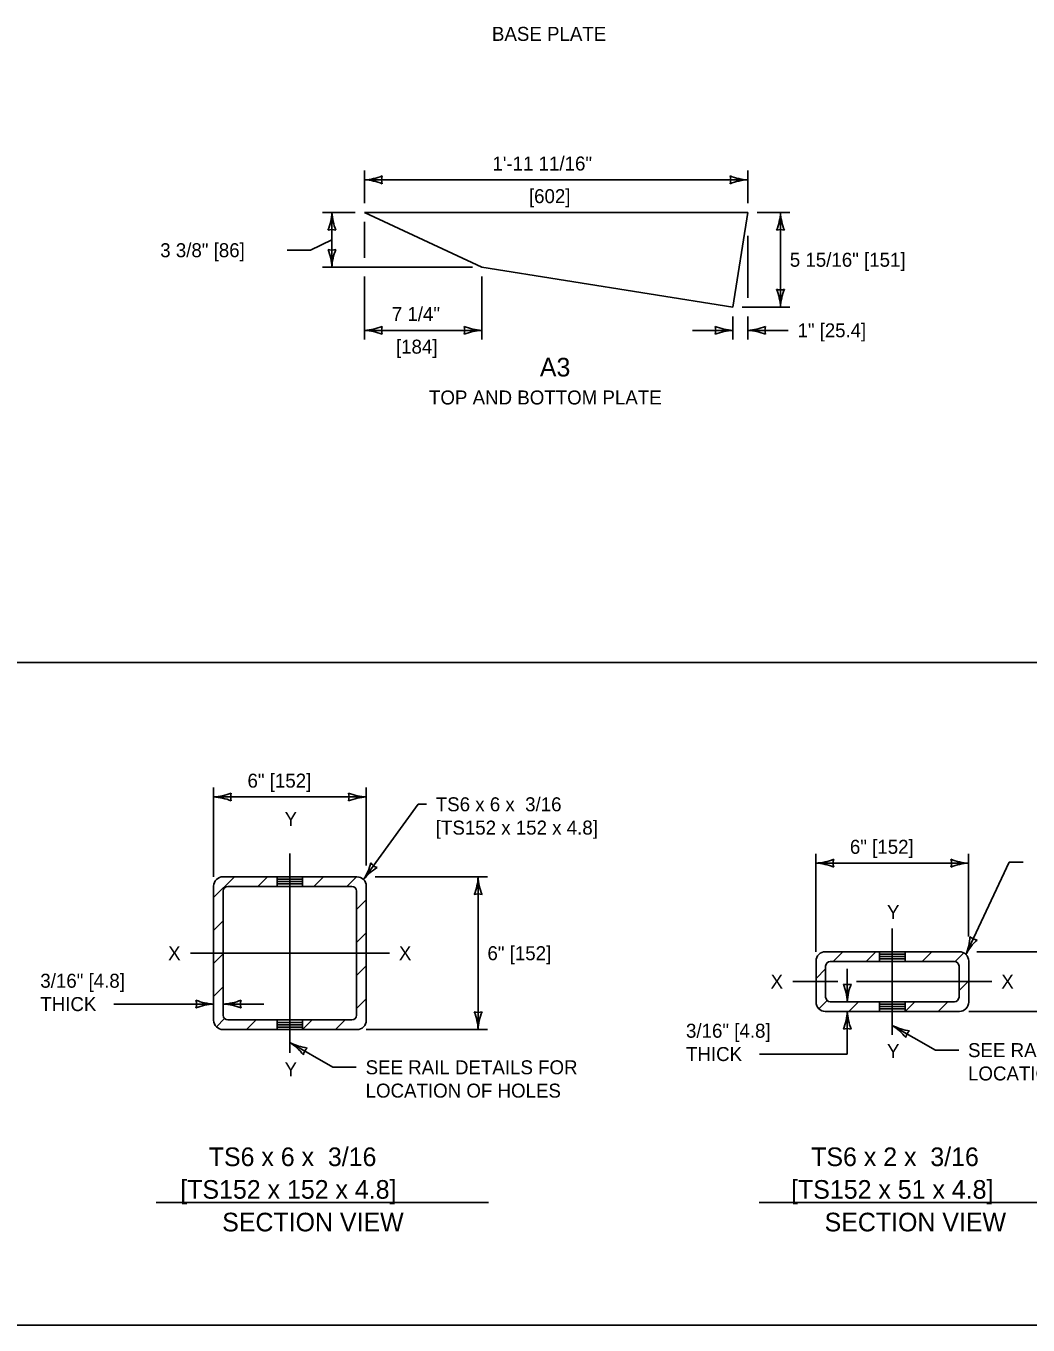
# Model space of a CAD drawing. Extents: x 49991.4 to 50021, y 49987.6 to 50011.4.
# Drawn here: x 50005.99 to 50010.29, y 49987.8 to 49993.37 of the extents above; entities that cross this region are included whole.
import ezdxf

# ---------------------------------------------------------------- set-up
doc = ezdxf.new("R2010")
doc.units = 0
for name, color, linetype in [('Level 1', 7, 'Continuous'), ('Level 2', 7, 'Continuous'), ('Level 3', 7, 'Continuous'), ('Level 4', 7, 'Continuous'), ('Level 5', 7, 'Continuous')]:
    doc.layers.add(name, color=color, linetype=linetype)

msp = doc.modelspace()

# ---------------------------------------------------------------- linework, layer by layer
at = {"layer": 'Level 1'}
for p, q in [((50009.0844, 49992.5698), (50007.4395, 49992.5698)), ((50007.9429, 49992.335), (50007.4395, 49992.5698)), ((50009.0844, 49992.5698), (50009.0202, 49992.1644)), ((50009.0202, 49992.1644), (50007.9429, 49992.335)), ((50005.9232, 49990.6395), (50016.7501, 49990.6395)), ((50006.7919, 49989.6315), (50006.8814, 49989.721)), ((50006.8319, 49989.721), (50007.407, 49989.7209)), ((50006.9814, 49989.6796), (50007.0228, 49989.721)), ((50007.0644, 49989.7102), (50007.1739, 49989.7102)), ((50007.0644, 49989.7002), (50007.1739, 49989.7002)), ((50007.0644, 49989.6902), (50007.1739, 49989.6902)), ((50007.222, 49989.6795), (50007.2634, 49989.7209)), ((50007.3634, 49989.6795), (50007.4048, 49989.7209)), ((50006.7919, 49989.681), (50006.7919, 49989.1058)), ((50006.8333, 49989.1271), (50006.8333, 49989.6596)), ((50006.8533, 49989.6796), (50007.3856, 49989.6795)), ((50007.4056, 49989.6595), (50007.4056, 49989.1272)), ((50007.447, 49989.6809), (50007.447, 49989.1057)), ((50007.4056, 49989.5802), (50007.447, 49989.6216)), ((50006.7919, 49989.49), (50006.8333, 49989.5314)), ((50007.4056, 49989.4388), (50007.447, 49989.4802)), ((50006.7919, 49989.3486), (50006.8333, 49989.39)), ((50009.3768, 49989.3598), (50009.3768, 49989.1836)), ((50009.4168, 49989.3998), (50009.9919, 49989.3998)), ((50009.4382, 49989.3584), (50009.9705, 49989.3584)), ((50009.4501, 49989.3584), (50009.4916, 49989.3998)), ((50009.5916, 49989.3584), (50009.633, 49989.3998)), ((50009.6495, 49989.3891), (50009.7589, 49989.3891)), ((50009.6495, 49989.3791), (50009.7589, 49989.3791)), ((50009.6495, 49989.3691), (50009.7589, 49989.3691)), ((50009.8323, 49989.3584), (50009.8737, 49989.3998)), ((50009.9735, 49989.3581), (50010.0105, 49989.3952)), ((50010.0319, 49989.3598), (50010.0319, 49989.1836)), ((50007.4056, 49989.2974), (50007.447, 49989.3388)), ((50009.3768, 49989.285), (50009.4182, 49989.3264)), ((50009.4182, 49989.205), (50009.4182, 49989.3384)), ((50009.9905, 49989.3384), (50009.9905, 49989.205)), ((50006.7919, 49989.2072), (50006.8333, 49989.2486)), ((50009.9905, 49989.2337), (50010.0319, 49989.2751)), ((50007.4056, 49989.156), (50007.447, 49989.1974)), ((50009.3885, 49989.1553), (50009.424, 49989.1909)), ((50009.4168, 49989.1436), (50009.9919, 49989.1436)), ((50009.9705, 49989.185), (50009.4382, 49989.185)), ((50009.5182, 49989.1436), (50009.5596, 49989.185)), ((50009.6495, 49989.1743), (50009.7589, 49989.1743)), ((50009.6495, 49989.1643), (50009.7589, 49989.1643)), ((50009.6495, 49989.1543), (50009.7589, 49989.1543)), ((50009.7589, 49989.1436), (50009.8004, 49989.185)), ((50009.9004, 49989.1436), (50009.9418, 49989.185)), ((50006.8036, 49989.0775), (50006.8391, 49989.113)), ((50007.3856, 49989.1072), (50006.8533, 49989.1071)), ((50006.9333, 49989.0658), (50006.9746, 49989.1071)), ((50007.0644, 49989.0964), (50007.1739, 49989.0964)), ((50007.0644, 49989.0864), (50007.1739, 49989.0864)), ((50007.1739, 49989.0658), (50007.2153, 49989.1072)), ((50007.3153, 49989.0657), (50007.3568, 49989.1072)), ((50007.407, 49989.0657), (50006.8319, 49989.0658)), ((50007.0644, 49989.0764), (50007.1739, 49989.0764))]:
    msp.add_line(p, q, dxfattribs=at)
msp.add_lwpolyline([(49999.3835, 49998.9992), (50016.7501, 49998.9992), (50016.7501, 49987.7988), (49999.3835, 49987.7988)], close=True, dxfattribs=at)
for centre, radius, start, end in [((50006.8319, 49989.681), 0.04, 90, 180), ((50007.407, 49989.6809), 0.04, 0, 90), ((50006.8533, 49989.6596), 0.02, 90, 180), ((50007.3856, 49989.6595), 0.02, 0, 90), ((50009.4168, 49989.3598), 0.04, 90, 180), ((50009.4382, 49989.3384), 0.02, 90, 180), ((50009.9705, 49989.3384), 0.02, 0, 90), ((50009.9919, 49989.3598), 0.04, 0, 90), ((50009.4382, 49989.205), 0.02, 180, 270), ((50009.9705, 49989.205), 0.02, 270, 0), ((50009.4168, 49989.1836), 0.04, 180, 270), ((50009.9919, 49989.1836), 0.04, 270, 0), ((50006.8319, 49989.1058), 0.04, 180, 270), ((50006.8533, 49989.1271), 0.02, 180, 270), ((50007.3856, 49989.1272), 0.02, 270, 0), ((50007.407, 49989.1057), 0.04, 270, 0)]:
    msp.add_arc(centre, radius, start, end, dxfattribs=at)
at = {"layer": 'Level 2'}
for p, q in [((50006.5456, 49988.3243), (50007.9708, 49988.3243)), ((50009.1328, 49988.3243), (50010.558, 49988.3243))]:
    msp.add_line(p, q, dxfattribs=at)
at = {"layer": 'Level 3'}
for p, q in [((50007.4395, 49992.6098), (50007.4395, 49992.7498)), ((50007.4395, 49992.7098), (50009.0844, 49992.7098)), ((50009.0844, 49992.6098), (50009.0844, 49992.7498)), ((50007.3995, 49992.5698), (50007.2595, 49992.5698)), ((50007.2995, 49992.5698), (50007.2995, 49992.335)), ((50009.1244, 49992.5698), (50009.2644, 49992.5698)), ((50009.2244, 49992.5698), (50009.2244, 49992.1644)), ((50007.4395, 49992.5298), (50007.4395, 49992.375)), ((50007.2995, 49992.4524), (50007.2071, 49992.408)), ((50009.0844, 49992.4698), (50009.0844, 49992.2044)), ((50007.2071, 49992.408), (50007.1071, 49992.408)), ((50007.9029, 49992.335), (50007.2595, 49992.335)), ((50007.4395, 49992.295), (50007.4395, 49992.0244)), ((50007.9429, 49992.295), (50007.9429, 49992.0244)), ((50009.0602, 49992.1644), (50009.2644, 49992.1644)), ((50009.0202, 49992.1244), (50009.0202, 49992.0244)), ((50009.0844, 49992.1244), (50009.0844, 49992.0244)), ((50007.4395, 49992.0644), (50007.9429, 49992.0644)), ((50009.0202, 49992.0644), (50008.8468, 49992.0644)), ((50009.0844, 49992.0644), (50009.2579, 49992.0644)), ((50006.7917, 49989.721), (50006.7917, 49990.1033)), ((50007.4468, 49989.7689), (50007.4468, 49990.1033)), ((50006.7917, 49990.0633), (50007.4468, 49990.0633)), ((50007.4352, 49989.7092), (50007.6694, 49990.0319)), ((50007.7051, 49990.0319), (50007.6694, 49990.0319)), ((50009.3767, 49989.3998), (50009.3767, 49989.8195)), ((50010.0318, 49989.4647), (50010.0318, 49989.8195)), ((50009.3767, 49989.7795), (50010.0318, 49989.7795)), ((50010.0202, 49989.3881), (50010.2061, 49989.7832)), ((50010.2658, 49989.7832), (50010.2061, 49989.7832)), ((50007.4851, 49989.7209), (50007.9668, 49989.7209)), ((50007.9268, 49989.7209), (50007.9268, 49989.0658)), ((50010.0667, 49989.3997), (50010.3698, 49989.3997)), ((50009.511, 49989.185), (50009.511, 49989.326)), ((50006.7919, 49989.1751), (50006.3634, 49989.1751)), ((50006.8333, 49989.1751), (50007.0067, 49989.1751)), ((50009.511, 49989.1436), (50009.511, 49988.9608)), ((50010.0319, 49989.1436), (50010.3698, 49989.1436)), ((50007.447, 49989.0658), (50007.9668, 49989.0658)), ((50009.1339, 49988.9608), (50009.511, 49988.9608))]:
    msp.add_line(p, q, dxfattribs=at)
for points in [[(50009.7042, 49989.0836), (50009.8891, 49988.9775), (50009.9891, 49988.9775)], [(50007.1192, 49989.01), (50007.304, 49988.904), (50007.404, 49988.904)]]:
    msp.add_lwpolyline(points, dxfattribs=at)
for centre, radius, start, end in [((50007.428, 49992.9425), 0.233, 272.8273, 292.0772), ((50007.4303, 49992.4877), 0.2223, 67.456, 87.6395), ((50007.5677, 49992.7098), 0.0548, 162.1388, 197.8612), ((50009.0936, 49992.9319), 0.2223, 247.456, 267.6395), ((50008.9562, 49992.7098), 0.0548, 342.1388, 17.8612), ((50009.0959, 49992.4771), 0.233, 92.8273, 112.0772), ((50007.0773, 49992.579), 0.2223, 337.456, 357.6395), ((50007.5322, 49992.5813), 0.233, 182.8273, 202.0772), ((50008.9917, 49992.5813), 0.233, 337.9228, 357.1727), ((50009.4466, 49992.579), 0.2223, 182.3605, 202.544), ((50007.2995, 49992.4416), 0.0548, 72.1388, 107.8612), ((50009.2244, 49992.4416), 0.0548, 72.1388, 107.8612), ((50007.2995, 49992.4632), 0.0548, 252.1388, 287.8612), ((50007.0668, 49992.3235), 0.233, 2.8273, 22.0772), ((50007.5216, 49992.3259), 0.2223, 157.456, 177.6395), ((50009.0023, 49992.1552), 0.2223, 2.3605, 22.544), ((50009.2244, 49992.2926), 0.0548, 252.1388, 287.8612), ((50009.4571, 49992.1529), 0.233, 157.9228, 177.1727), ((50007.428, 49992.2971), 0.233, 272.8273, 292.0772), ((50007.4303, 49991.8423), 0.2223, 67.456, 87.6395), ((50007.5677, 49992.0644), 0.0548, 162.1388, 197.8612), ((50007.9521, 49992.2865), 0.2223, 247.456, 267.6395), ((50007.8147, 49992.0644), 0.0548, 342.1388, 17.8612), ((50007.9544, 49991.8317), 0.233, 92.8273, 112.0772), ((50009.0294, 49992.2865), 0.2223, 247.456, 267.6395), ((50008.892, 49992.0644), 0.0548, 342.1388, 17.8612), ((50009.0317, 49991.8317), 0.233, 92.8273, 112.0772), ((50009.0729, 49992.2971), 0.233, 272.8273, 292.0772), ((50009.0753, 49991.8423), 0.2223, 67.456, 87.6395), ((50009.2126, 49992.0644), 0.0548, 162.1388, 197.8612), ((50006.7802, 49990.2961), 0.233, 272.8273, 292.0772), ((50006.9199, 49990.0633), 0.0548, 162.1388, 197.8612), ((50007.4559, 49990.2855), 0.2223, 247.456, 267.6395), ((50007.3186, 49990.0633), 0.0548, 342.1388, 17.8612), ((50006.7825, 49989.8412), 0.2223, 67.456, 87.6395), ((50007.4583, 49989.8306), 0.233, 92.8273, 112.0772), ((50007.2401, 49989.8366), 0.233, 326.8617, 346.1116), ((50007.6097, 49989.5713), 0.2223, 121.4904, 141.6739), ((50007.5105, 49989.813), 0.0548, 216.1732, 251.8956), ((50009.3652, 49990.0122), 0.233, 272.8273, 292.0772), ((50009.3676, 49989.5573), 0.2223, 67.456, 87.6395), ((50009.5049, 49989.7795), 0.0548, 162.1388, 197.8612), ((50010.041, 49990.0016), 0.2223, 247.456, 267.6395), ((50009.9036, 49989.7795), 0.0548, 342.1388, 17.8612), ((50010.0433, 49989.5467), 0.233, 92.8273, 112.0772), ((50007.7046, 49989.73), 0.2223, 337.456, 357.6395), ((50008.1595, 49989.7323), 0.233, 182.8273, 202.0772), ((50007.9268, 49989.5926), 0.0548, 72.1388, 107.8612), ((50009.8047, 49989.4767), 0.233, 337.6348, 356.8846), ((50010.2173, 49989.2852), 0.2223, 132.2635, 152.447), ((50010.0748, 49989.5041), 0.0548, 226.9463, 262.6686), ((50009.511, 49989.3132), 0.0548, 252.1388, 287.8612), ((50009.2783, 49989.1735), 0.233, 2.8273, 22.0772), ((50009.7331, 49989.1758), 0.2223, 157.456, 177.6395), ((50006.801, 49989.3973), 0.2223, 247.456, 267.6395), ((50006.6636, 49989.1751), 0.0548, 342.1388, 17.8612), ((50006.8218, 49989.4078), 0.233, 272.8273, 292.0772), ((50006.9615, 49989.1751), 0.0548, 162.1388, 197.8612), ((50006.8034, 49988.9424), 0.233, 92.8273, 112.0772), ((50006.8241, 49988.953), 0.2223, 67.456, 87.6395), ((50007.9268, 49989.194), 0.0548, 252.1388, 287.8612), ((50007.6941, 49989.0543), 0.233, 2.8273, 22.0772), ((50008.1489, 49989.0566), 0.2223, 157.456, 177.6395), ((50009.2888, 49989.1527), 0.2223, 337.456, 357.6395), ((50009.7437, 49989.1551), 0.233, 182.8273, 202.0772), ((50009.5857, 49988.8955), 0.2223, 37.6107, 57.7942), ((50009.8101, 49989.2912), 0.233, 242.982, 262.2318), ((50009.511, 49989.0154), 0.0548, 72.1388, 107.8612), ((50009.8154, 49989.0198), 0.0548, 132.2935, 168.0159), ((50007.0007, 49988.8219), 0.2223, 37.6107, 57.7942), ((50007.225, 49989.2176), 0.233, 242.982, 262.2318), ((50007.2304, 49988.9462), 0.0548, 132.2935, 168.0159)]:
    msp.add_arc(centre, radius, start, end, dxfattribs=at)
at = {"layer": 'Level 4'}
for p, q in [((50007.0644, 49989.721), (50007.0644, 49989.6796)), ((50007.1739, 49989.721), (50007.1739, 49989.6796)), ((50009.6495, 49989.3998), (50009.6495, 49989.3584)), ((50009.7589, 49989.3998), (50009.7589, 49989.3584)), ((50009.6495, 49989.1436), (50009.6495, 49989.185)), ((50009.7589, 49989.185), (50009.7589, 49989.1436)), ((50007.0644, 49989.1072), (50007.0644, 49989.0658)), ((50007.1739, 49989.1072), (50007.1739, 49989.0658))]:
    msp.add_line(p, q, dxfattribs=at)
at = {"layer": 'Level 5'}
for p, q in [((50007.1192, 49988.9658), (50007.1192, 49989.821)), ((50009.7042, 49989.0436), (50009.7042, 49989.4998)), ((50006.6919, 49989.3933), (50007.547, 49989.3933)), ((50009.2768, 49989.2716), (50009.471, 49989.2716)), ((50009.551, 49989.2716), (50010.1319, 49989.2716))]:
    msp.add_line(p, q, dxfattribs=at)

# ---------------------------------------------------------------- texts
at = {"layer": 'Level 2'}
for s, height, p in [('BASE PLATE', 0.06, (50007.9862, 49993.3058)), ('1\'-11 11/16"', 0.06, (50007.9883, 49992.7498)), ('[602]', 0.06, (50008.1448, 49992.6098)), ('3 3/8" [86]', 0.06, (50006.5626, 49992.378)), ('5 15/16" [151]', 0.06, (50009.2644, 49992.3371)), ('7 1/4"', 0.06, (50007.5565, 49992.1044)), ('1" [25.4]', 0.05957, (50009.2979, 49992.0346)), ('[184]', 0.06, (50007.5741, 49991.9644)), ('A3', 0.08, (50008.1917, 49991.8665)), ('TOP AND BOTTOM PLATE', 0.06, (50007.716, 49991.7465)), ('6" [152]', 0.06, (50006.9371, 49990.1033)), ('TS6 x 6 x  3/16 ', 0.06, (50007.7451, 49990.0019)), ('Y', 0.06, (50007.0963, 49989.9393)), ('[TS152 x 152 x 4.8]', 0.06, (50007.7451, 49989.9019)), ('6" [152]', 0.06, (50009.5222, 49989.8195)), ('Y', 0.06, (50009.6814, 49989.5398)), ('X', 0.06, (50006.5966, 49989.3633)), ('X', 0.06, (50007.5868, 49989.3633)), ('6" [152]', 0.06, (50007.9668, 49989.3633)), ('3/16" [4.8]', 0.06, (50006.0481, 49989.2451)), ('X', 0.06, (50009.1818, 49989.2417)), ('X', 0.06, (50010.1719, 49989.2416)), ('THICK', 0.06, (50006.0481, 49989.1451)), ('3/16" [4.8]', 0.06, (50008.8189, 49989.0308)), ('THICK', 0.06, (50008.8189, 49988.9308)), ('Y', 0.06, (50009.6814, 49988.9436)), ('Y', 0.06, (50007.0963, 49988.8658)), ('TS6 x 6 x  3/16 ', 0.08, (50006.7709, 49988.4803)), ('TS6 x 2 x  3/16 ', 0.08, (50009.3561, 49988.4803)), ('[TS152 x 152 x 4.8]', 0.08, (50006.6488, 49988.3403)), ('[TS152 x 51 x 4.8]', 0.08, (50009.2699, 49988.3403)), ('SECTION VIEW', 0.08, (50006.8286, 49988.2003)), ('SECTION VIEW', 0.08, (50009.4137, 49988.2003))]:
    msp.add_text(s, height=height, dxfattribs=at).set_placement(p)
for s, p in [('SEE RAIL DETAILS FOR', (50010.0291, 49988.9475)), ('SEE RAIL DETAILS FOR', (50007.444, 49988.874)), ('LOCATION OF HOLES', (50010.0291, 49988.8475)), ('LOCATION OF HOLES', (50007.444, 49988.774))]:
    msp.add_text(s, height=0.06, rotation=360, dxfattribs=at).set_placement(p)

doc.saveas('drawing.dxf')
